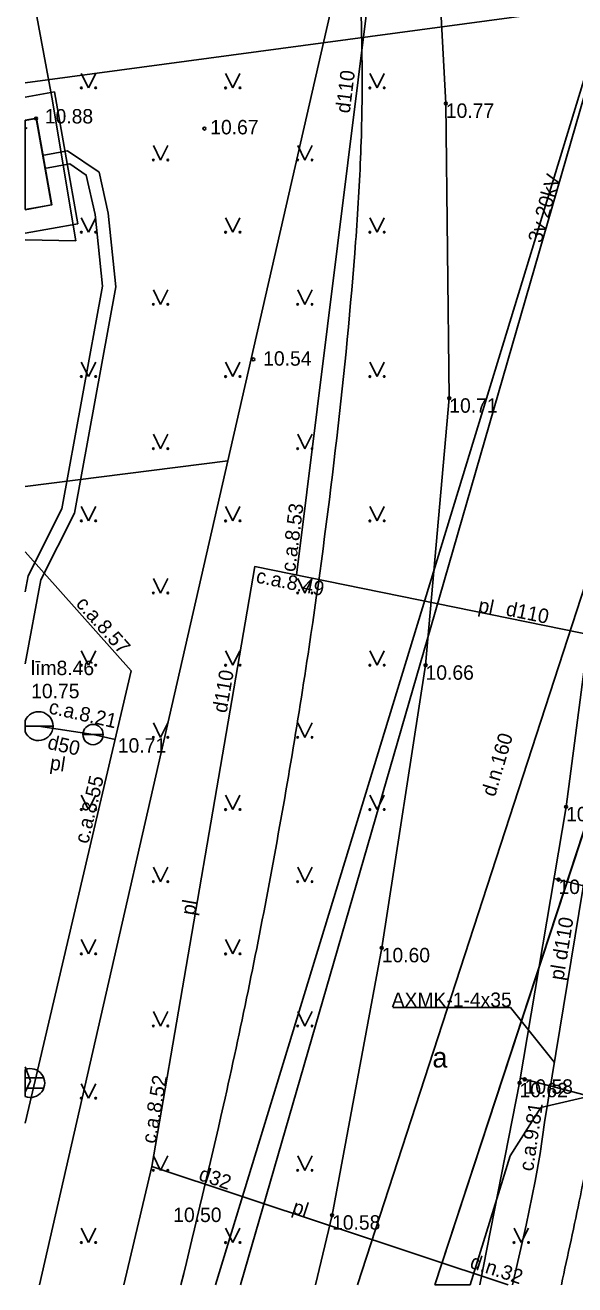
# Model space of a CAD drawing. Extents: x 502312.8 to 502402.4, y 308528.5 to 308602.
# Drawn here: x 502312.81 to 502331.86, y 308528.54 to 308572.17 of the extents above; entities that cross this region are included whole.
import ezdxf

# ---------------------------------------------------------------- set-up
doc = ezdxf.new("R2010")
doc.units = 0
for name, color, linetype in [('24', 7, 'Continuous'), ('25', 7, 'Continuous'), ('38', 7, 'Continuous'), ('42', 7, 'Continuous'), ('APGR_SARK_####_####_#', 7, 'Continuous'), ('BUVE_EKAS_####_####_#', 7, 'Continuous'), ('CELI_CAPM_####_####_#', 7, 'Continuous'), ('CELI_CMAL_####_####_#', 7, 'Continuous'), ('CELI_CSEG_####_TKST_#', 7, 'Continuous'), ('CKOM_ZEMJ_####_####_#', 7, 'Continuous'), ('ELEK_ACRL_####_####_#', 7, 'Continuous'), ('ELEK_ACRL_####_TKST_#', 7, 'Continuous'), ('ELEK_VADP_ZSPR_####_#', 7, 'Continuous'), ('ELEK_VADP_ZSPR_####_I', 7, 'Continuous'), ('ELEK_VADP_ZSPR_TKST_I', 7, 'Continuous'), ('ELEK_VADV_VSPR_####_#', 7, 'Continuous'), ('ELEK_VADV_VSPR_TKST_#', 7, 'Continuous'), ('GAZE_VADP_VSP2_####_#', 7, 'Continuous'), ('GAZE_VADP_VSP2_TKST_#', 7, 'Continuous'), ('LKAN_ELEM_####_####_#', 7, 'Continuous'), ('LKAN_VADP_PAST_####_#', 7, 'Continuous'), ('NORB_ZOGS_ZSTP_####_#', 7, 'Continuous'), ('RELJ_AATZ_####_TKST_#', 7, 'Continuous'), ('RELJ_ELEM_####_####_#', 7, 'Continuous'), ('TERT_ELEM_####_####_#', 7, 'Continuous'), ('TERT_KONT_####_####_#', 7, 'Continuous'), ('UDTK_ELEM_####_####_#', 7, 'Continuous'), ('UDTK_ELEM_####_TKST_#', 7, 'Continuous'), ('UDTK_VADP_UDEN_####_#', 7, 'Continuous'), ('UDTK_VADP_UDEN_####_I', 7, 'Continuous'), ('UDTK_VADP_UDEN_TKST_#', 7, 'Continuous'), ('UDTK_VADP_UDEN_TKST_I', 7, 'Continuous')]:
    doc.layers.add(name, color=color, linetype=linetype)

msp = doc.modelspace()

# ---------------------------------------------------------------- linework, layer by layer
at = {"layer": '24'}
msp.add_line((502335.708, 308581.855), (502319.397, 308528.536), dxfattribs=at)
at = {"layer": '25'}
msp.add_line((502332.854, 308546.354), (502326.998, 308528.536), dxfattribs=at)
at = {"layer": '38'}
msp.add_line((502326.998, 308528.536), (502328.224, 308528.536), dxfattribs=at)
msp.add_lwpolyline([(502328.224, 308528.536), (502329.609, 308533.009), (502330.682, 308534.676), (502332.615, 308535.133), (502333.728, 308534.236), (502334.709, 308533.035), (502336.102, 308537.277), (502335.188, 308538.312), (502334.662, 308540.178), (502334.007, 308541.362), (502336.859, 308546.631), (502332.854, 308546.354), (502326.998, 308528.536)], dxfattribs=at)
at = {"layer": '42'}
msp.add_line((502312.806, 308568.882), (502312.806, 308565.785), dxfattribs=at)
msp.add_lwpolyline([(502312.806, 308565.785), (502313.732, 308565.948), (502313.202, 308568.952), (502312.806, 308568.882)], dxfattribs=at)
at = {"layer": 'APGR_SARK_####_####_#'}
msp.add_line((502312.806, 308570.179), (502363.114, 308576.934), dxfattribs=at)
at = {"layer": 'BUVE_EKAS_####_####_#'}
for p, q in [((502313.182, 308568.937), (502312.806, 308568.868)), ((502313.721, 308565.944), (502313.182, 308568.937)), ((502312.806, 308565.776), (502313.721, 308565.944))]:
    msp.add_line(p, q, dxfattribs=at)
at = {"layer": 'CELI_CAPM_####_####_#'}
for points in [[(502333.247, 308585.455), (502332.69, 308583.567), (502332.386, 308581.064), (502332.443, 308578.267), (502332.941, 308569.242), (502333.087, 308561.281), (502332.758, 308554.275), (502331.553, 308545.092), (502329.94, 308535.531), (502328.563, 308528.536)], [(502322.863, 308528.536), (502323.443, 308530.946), (502325.163, 308540.207), (502326.683, 308549.996), (502327.505, 308559.246), (502327.386, 308569.461), (502326.881, 308578.901), (502326.764, 308580.205)], [(502312.806, 308574.649), (502313.726, 308569.672), (502314.559, 308564.701), (502312.806, 308564.738)]]:
    msp.add_lwpolyline(points, dxfattribs=at)
at = {"layer": 'CELI_CMAL_####_####_#'}
for points in [[(502331.135, 308542.611), (502337.342, 308541.065)], [(502337.342, 308541.065), (502334.68, 308533.31), (502332.714, 308534.975), (502329.967, 308535.693)]]:
    msp.add_lwpolyline(points, dxfattribs=at)
at = {"layer": 'CKOM_ZEMJ_####_####_#'}
msp.add_lwpolyline([(502312.806, 308564.972), (502314.628, 308565.294), (502313.822, 308569.857), (502312.806, 308569.678)], dxfattribs=at)
at = {"layer": 'ELEK_ACRL_####_####_#'}
for points in [[(502312.806, 308550.053), (502313.352, 308552.952), (502314.52, 308555.27), (502315.946, 308563.112), (502315.685, 308565.657), (502315.374, 308567.078), (502315.374, 308567.078), (502314.269, 308567.816), (502314.269, 308567.816), (502313.397, 308567.662)], [(502312.806, 308552.538), (502312.912, 308553.101), (502314.079, 308555.418), (502315.482, 308563.13), (502315.227, 308565.61), (502314.924, 308566.978), (502314.924, 308566.978), (502314.349, 308567.363), (502314.349, 308567.363), (502313.477, 308567.209)], [(502333.168, 308548.776), (502332.753, 308546.121), (502332.522, 308544.631), (502330.809, 308534.157), (502330.652, 308533.084), (502330.485, 308532.13), (502330.174, 308530.605), (502329.701, 308528.536)]]:
    msp.add_lwpolyline(points, dxfattribs=at)
at = {"layer": 'ELEK_VADP_ZSPR_####_#'}
for points in [[(502312.806, 308550.053), (502313.352, 308552.952), (502314.52, 308555.27), (502315.946, 308563.112), (502315.685, 308565.657), (502315.374, 308567.078), (502315.374, 308567.078), (502314.269, 308567.816), (502314.269, 308567.816), (502313.397, 308567.662)], [(502312.806, 308552.538), (502312.912, 308553.101), (502314.079, 308555.418), (502315.482, 308563.13), (502315.227, 308565.61), (502314.924, 308566.978), (502314.924, 308566.978), (502314.349, 308567.363), (502314.349, 308567.363), (502313.477, 308567.209)]]:
    msp.add_lwpolyline(points, dxfattribs=at)
at = {"layer": 'ELEK_VADP_ZSPR_####_I'}
msp.add_lwpolyline([(502333.168, 308548.776), (502332.753, 308546.121), (502332.522, 308544.631), (502330.809, 308534.157), (502330.652, 308533.084), (502330.485, 308532.13), (502330.174, 308530.605), (502329.701, 308528.536)], dxfattribs=at)
at = {"layer": 'ELEK_VADP_ZSPR_TKST_I'}
for p, q in [((502325.553, 308538.146), (502329.631, 308538.146)), ((502329.631, 308538.146), (502331.149, 308536.237))]:
    msp.add_line(p, q, dxfattribs=at)
at = {"layer": 'ELEK_VADV_VSPR_####_#'}
msp.add_lwpolyline([(502320.263, 308528.536), (502327.011, 308551.84), (502335.944, 308582.765)], dxfattribs=at)
at = {"layer": 'GAZE_VADP_VSP2_####_#'}
msp.add_line((502324.325, 308528.536), (502342.183, 308583.46), dxfattribs=at)
at = {"layer": 'LKAN_ELEM_####_####_#'}
for p, q in [((502312.806, 308535.994), (502312.806, 308535.058)), ((502312.806, 308535.701), (502313.45, 308535.701)), ((502312.806, 308535.351), (502313.45, 308535.351))]:
    msp.add_line(p, q, dxfattribs=at)
msp.add_arc((502312.982, 308535.526), 0.5, 249.3964, 110.6036, dxfattribs=at)
at = {"layer": 'LKAN_VADP_PAST_####_#'}
msp.add_line((502312.806, 308535.21), (502312.989, 308535.596), dxfattribs=at)
for points in [[(502312.806, 308568.631), (502312.87, 308568.595)], [(502312.806, 308536.09), (502312.989, 308535.596)]]:
    msp.add_lwpolyline(points, dxfattribs=at)
at = {"layer": 'NORB_ZOGS_ZSTP_####_#'}
for points in [[(502313.304, 308528.536), (502319.831, 308557.078), (502324.272, 308576.524)], [(502312.806, 308556.196), (502319.831, 308557.078)]]:
    msp.add_lwpolyline(points, dxfattribs=at)
at = {"layer": 'RELJ_ELEM_####_####_#'}
for centre in [(502327.386, 308569.461), (502313.182, 308568.937), (502319.017, 308568.588), (502320.713, 308560.594), (502327.505, 308559.246), (502326.683, 308549.996), (502331.553, 308545.092), (502331.289, 308542.573), (502325.163, 308540.207), (502330.115, 308535.654), (502329.94, 308535.531), (502323.443, 308530.946)]:
    msp.add_circle(centre, 0.05, dxfattribs=at)
at = {"layer": 'TERT_ELEM_####_####_#'}
for p, q in [((502314.75, 308570.5), (502315, 308570)), ((502315, 308570), (502315.25, 308570.5)), ((502319.75, 308570.5), (502320, 308570)), ((502320, 308570), (502320.25, 308570.5)), ((502324.75, 308570.5), (502325, 308570)), ((502325, 308570), (502325.25, 308570.5)), ((502317.25, 308568), (502317.5, 308567.5)), ((502317.5, 308567.5), (502317.75, 308568)), ((502322.25, 308568), (502322.5, 308567.5)), ((502322.5, 308567.5), (502322.75, 308568)), ((502314.75, 308565.5), (502315, 308565)), ((502315, 308565), (502315.25, 308565.5)), ((502319.75, 308565.5), (502320, 308565)), ((502320, 308565), (502320.25, 308565.5)), ((502324.75, 308565.5), (502325, 308565)), ((502325, 308565), (502325.25, 308565.5)), ((502317.25, 308563), (502317.5, 308562.5)), ((502317.5, 308562.5), (502317.75, 308563)), ((502322.25, 308563), (502322.5, 308562.5)), ((502322.5, 308562.5), (502322.75, 308563)), ((502314.75, 308560.5), (502315, 308560)), ((502315, 308560), (502315.25, 308560.5)), ((502319.75, 308560.5), (502320, 308560)), ((502320, 308560), (502320.25, 308560.5)), ((502324.75, 308560.5), (502325, 308560)), ((502325, 308560), (502325.25, 308560.5)), ((502317.25, 308558), (502317.5, 308557.5)), ((502317.5, 308557.5), (502317.75, 308558)), ((502322.25, 308558), (502322.5, 308557.5)), ((502322.5, 308557.5), (502322.75, 308558)), ((502314.75, 308555.5), (502315, 308555)), ((502315, 308555), (502315.25, 308555.5)), ((502319.75, 308555.5), (502320, 308555)), ((502320, 308555), (502320.25, 308555.5)), ((502324.75, 308555.5), (502325, 308555)), ((502325, 308555), (502325.25, 308555.5)), ((502317.25, 308553), (502317.5, 308552.5)), ((502317.5, 308552.5), (502317.75, 308553)), ((502322.25, 308553), (502322.5, 308552.5)), ((502322.5, 308552.5), (502322.75, 308553)), ((502314.75, 308550.5), (502315, 308550)), ((502315, 308550), (502315.25, 308550.5)), ((502319.75, 308550.5), (502320, 308550)), ((502320, 308550), (502320.25, 308550.5)), ((502324.75, 308550.5), (502325, 308550)), ((502325, 308550), (502325.25, 308550.5)), ((502317.25, 308548), (502317.5, 308547.5)), ((502317.5, 308547.5), (502317.75, 308548)), ((502322.25, 308548), (502322.5, 308547.5)), ((502322.5, 308547.5), (502322.75, 308548)), ((502314.75, 308545.5), (502315, 308545)), ((502315, 308545), (502315.25, 308545.5)), ((502319.75, 308545.5), (502320, 308545)), ((502320, 308545), (502320.25, 308545.5)), ((502324.75, 308545.5), (502325, 308545)), ((502325, 308545), (502325.25, 308545.5)), ((502317.25, 308543), (502317.5, 308542.5)), ((502317.5, 308542.5), (502317.75, 308543)), ((502322.25, 308543), (502322.5, 308542.5)), ((502322.5, 308542.5), (502322.75, 308543)), ((502314.75, 308540.5), (502315, 308540)), ((502315, 308540), (502315.25, 308540.5)), ((502319.75, 308540.5), (502320, 308540)), ((502320, 308540), (502320.25, 308540.5)), ((502317.25, 308538), (502317.5, 308537.5)), ((502317.5, 308537.5), (502317.75, 308538)), ((502322.25, 308538), (502322.5, 308537.5)), ((502322.5, 308537.5), (502322.75, 308538)), ((502314.75, 308535.5), (502315, 308535)), ((502315, 308535), (502315.25, 308535.5)), ((502317.25, 308533), (502317.5, 308532.5)), ((502317.5, 308532.5), (502317.75, 308533)), ((502322.25, 308533), (502322.5, 308532.5)), ((502322.5, 308532.5), (502322.75, 308533)), ((502314.75, 308530.5), (502315, 308530)), ((502315, 308530), (502315.25, 308530.5)), ((502319.75, 308530.5), (502320, 308530)), ((502320, 308530), (502320.25, 308530.5)), ((502329.75, 308530.5), (502330, 308530)), ((502330, 308530), (502330.25, 308530.5))]:
    msp.add_line(p, q, dxfattribs=at)
for centre, radius in [((502314.75, 308570), 0.028), ((502315.25, 308570), 0.0263), ((502319.75, 308570), 0.028), ((502320.25, 308570), 0.0263), ((502324.75, 308570), 0.028), ((502325.25, 308570), 0.0263), ((502317.25, 308567.5), 0.028), ((502317.75, 308567.5), 0.0263), ((502322.25, 308567.5), 0.028), ((502322.75, 308567.5), 0.0263), ((502314.75, 308565), 0.028), ((502315.25, 308565), 0.0263), ((502319.75, 308565), 0.028), ((502320.25, 308565), 0.0263), ((502324.75, 308565), 0.028), ((502325.25, 308565), 0.0263), ((502317.25, 308562.5), 0.028), ((502317.75, 308562.5), 0.0263), ((502322.25, 308562.5), 0.028), ((502322.75, 308562.5), 0.0263), ((502314.75, 308560), 0.028), ((502315.25, 308560), 0.0263), ((502319.75, 308560), 0.028), ((502320.25, 308560), 0.0263), ((502324.75, 308560), 0.028), ((502325.25, 308560), 0.0263), ((502317.25, 308557.5), 0.028), ((502317.75, 308557.5), 0.0263), ((502322.25, 308557.5), 0.028), ((502322.75, 308557.5), 0.0263), ((502314.75, 308555), 0.028), ((502315.25, 308555), 0.0263), ((502319.75, 308555), 0.028), ((502320.25, 308555), 0.0263), ((502324.75, 308555), 0.028), ((502325.25, 308555), 0.0263), ((502317.25, 308552.5), 0.028), ((502317.75, 308552.5), 0.0263), ((502322.25, 308552.5), 0.028), ((502322.75, 308552.5), 0.0263), ((502314.75, 308550), 0.028), ((502315.25, 308550), 0.0263), ((502319.75, 308550), 0.028), ((502320.25, 308550), 0.0263), ((502324.75, 308550), 0.028), ((502325.25, 308550), 0.0263), ((502317.25, 308547.5), 0.028), ((502317.75, 308547.5), 0.0263), ((502322.25, 308547.5), 0.028), ((502322.75, 308547.5), 0.0263), ((502314.75, 308545), 0.028), ((502315.25, 308545), 0.0263), ((502319.75, 308545), 0.028), ((502320.25, 308545), 0.0263), ((502324.75, 308545), 0.028), ((502325.25, 308545), 0.0263), ((502317.25, 308542.5), 0.028), ((502317.75, 308542.5), 0.0263), ((502322.25, 308542.5), 0.028), ((502322.75, 308542.5), 0.0263), ((502314.75, 308540), 0.028), ((502315.25, 308540), 0.0263), ((502319.75, 308540), 0.028), ((502320.25, 308540), 0.0263), ((502317.25, 308537.5), 0.028), ((502317.75, 308537.5), 0.0263), ((502322.25, 308537.5), 0.028), ((502322.75, 308537.5), 0.0263), ((502314.75, 308535), 0.028), ((502315.25, 308535), 0.0263), ((502317.25, 308532.5), 0.028), ((502317.75, 308532.5), 0.0263), ((502322.25, 308532.5), 0.028), ((502322.75, 308532.5), 0.0263), ((502314.75, 308530), 0.028), ((502315.25, 308530), 0.0263), ((502319.75, 308530), 0.028), ((502320.25, 308530), 0.0263), ((502329.75, 308530), 0.028), ((502330.25, 308530), 0.0263)]:
    msp.add_circle(centre, radius, dxfattribs=at)
at = {"layer": 'TERT_KONT_####_####_#'}
for points in [[(502318.205, 308528.536), (502319.679, 308534.76), (502321.307, 308542.669), (502322.012, 308546.644), (502322.648, 308550.634), (502323.554, 308557.442), (502324.228, 308564.274), (502324.421, 308567.369), (502324.483, 308570.471), (502324.437, 308573.576), (502324.307, 308576.676), (502324.156, 308577.514), (502323.545, 308579.414), (502323.104, 308580.32), (502322.532, 308581.216), (502322.254, 308581.408), (502320.377, 308581.216), (502318.497, 308580.974), (502314.744, 308580.405), (502312.957, 308580.12)], [(502331.389, 308528.536), (502332.049, 308531.622), (502332.714, 308534.975)]]:
    msp.add_spline(points, degree=3, dxfattribs=at)
at = {"layer": 'UDTK_ELEM_####_####_#'}
for p, q in [((502312.806, 308548.073), (502312.806, 308547.708)), ((502312.806, 308547.89), (502313.771, 308547.89)), ((502314.806, 308547.597), (502315.509, 308547.597))]:
    msp.add_line(p, q, dxfattribs=at)
msp.add_circle((502315.157, 308547.597), 0.351, dxfattribs=at)
msp.add_arc((502313.271, 308547.89), 0.5, 201.4458, 158.5542, dxfattribs=at)
at = {"layer": 'UDTK_VADP_UDEN_####_#'}
for points in [[(502312.806, 308553.922), (502316.481, 308549.809)], [(502316.23, 308528.536), (502317.192, 308532.639), (502320.764, 308553.416), (502338.976, 308549.714)], [(502312.806, 308534.137), (502316.481, 308549.809)], [(502315.922, 308547.424), (502315.157, 308547.597), (502313.27, 308547.89)], [(502317.192, 308532.639), (502329.542, 308528.536)]]:
    msp.add_lwpolyline(points, dxfattribs=at)
at = {"layer": 'UDTK_VADP_UDEN_####_I'}
msp.add_line((502322.212, 308553.122), (502325.125, 308576.488), dxfattribs=at)

# ---------------------------------------------------------------- texts
at = {"layer": 'CELI_CSEG_####_TKST_#'}
msp.add_text('a', height=0.7, dxfattribs=at).set_placement((502326.92, 308536.062))
at = {"layer": 'ELEK_ACRL_####_TKST_#'}
for s, rotation, p in [('pl d110', 80.7102, (502331.459, 308539.064)), ('c.a.9.81', 81.7306, (502330.409, 308532.451))]:
    msp.add_text(s, height=0.5, rotation=rotation, dxfattribs=at).set_placement(p)
at = {"layer": 'ELEK_VADP_ZSPR_TKST_I'}
msp.add_text('AXMK-1-4x35', height=0.5, dxfattribs=at).set_placement((502325.507, 308538.161))
at = {"layer": 'ELEK_VADV_VSPR_TKST_#'}
msp.add_text('3v 20kV', height=0.5, rotation=73.8881, dxfattribs=at).set_placement((502330.697, 308564.6))
at = {"layer": 'GAZE_VADP_VSP2_TKST_#'}
msp.add_text('d.n.160', height=0.5, rotation=73.6052, dxfattribs=at).set_placement((502329.087, 308545.418))
at = {"layer": 'RELJ_AATZ_####_TKST_#'}
for s, p in [('10.77', (502327.386, 308568.961)), ('10.88', (502313.487, 308568.766)), ('10.67', (502319.221, 308568.389)), ('10.54', (502321.055, 308560.376)), ('10.71', (502327.505, 308558.746)), ('10.66', (502326.683, 308549.496)), ('10.65', (502331.553, 308544.592)), ('10.61', (502331.289, 308542.073)), ('10.60', (502325.163, 308539.707)), ('10.62', (502329.94, 308535.031)), ('10.58', (502330.115, 308535.154)), ('10.50', (502317.937, 308530.71)), ('10.58', (502323.443, 308530.446))]:
    msp.add_text(s, height=0.5, dxfattribs=at).set_placement(p)
at = {"layer": 'UDTK_ELEM_####_TKST_#'}
for s, p in [('līm8.46', (502313.002, 308549.656)), ('10.75', (502313.014, 308548.855)), ('10.71', (502316.017, 308546.971))]:
    msp.add_text(s, height=0.5, dxfattribs=at).set_placement(p)
at = {"layer": 'UDTK_VADP_UDEN_TKST_#'}
for s, rotation, p in [('c.a.8.49', 348.509, (502320.78, 308552.866)), ('c.a.8.57', 311.7819, (502314.536, 308552.108)), ('pl', 348.509, (502328.481, 308551.847)), ('d110', 348.509, (502329.441, 308551.727)), ('d110', 80.245, (502319.787, 308548.325)), ('c.a.8.21', 347.2538, (502313.594, 308548.336)), ('d50', 347.2538, (502313.551, 308547.109)), ('pl', 351.1882, (502313.64, 308546.39)), ('c.a.8.55', 76.7604, (502314.99, 308543.791)), ('pl', 80.245, (502318.683, 308541.313)), ('c.a.8.52', 80.245, (502317.324, 308533.405)), ('d32', 341.6203, (502318.787, 308532.172)), ('pl', 341.6203, (502322.027, 308531.032)), ('d.n.32', 341.6203, (502328.188, 308529.135))]:
    msp.add_text(s, height=0.5, rotation=rotation, dxfattribs=at).set_placement(p)
at = {"layer": 'UDTK_VADP_UDEN_TKST_I'}
for s, p in [('d110', (502324.054, 308569.103)), ('c.a.8.53', (502322.161, 308553.214))]:
    msp.add_text(s, height=0.5, rotation=82.8936, dxfattribs=at).set_placement(p)

doc.saveas('drawing.dxf')
